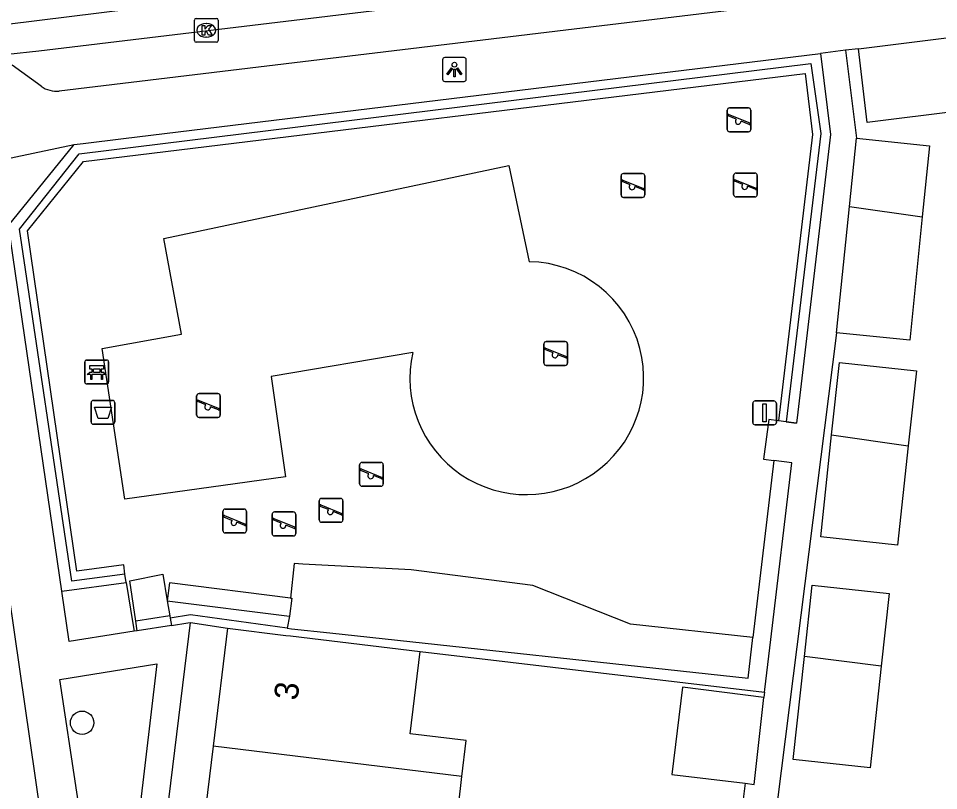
# Model space of a CAD drawing. Extents: x 162172 to 163187, y 382874 to 383684.
# Drawn here: x 162789.24 to 162827.76, y 383231.49 to 383263.83 of the extents above; entities that cross this region are included whole.
import ezdxf

# ---------------------------------------------------------------- set-up
doc = ezdxf.new("R2010")
doc.units = 0
for name, color, linetype in [('IMGEO_Afvalbak', 7, 'Continuous'), ('IMGEO_Bank', 7, 'Continuous'), ('IMGEO_Boom', 7, 'Continuous'), ('IMGEO_Groenvoorziening', 7, 'Continuous'), ('IMGEO_Haag', 7, 'Continuous'), ('IMGEO_Kolk', 7, 'Continuous'), ('IMGEO_Lichtpunt', 7, 'Continuous'), ('IMGEO_Pand', 7, 'Continuous'), ('IMGEO_Pand_nummerreeks', 7, 'Continuous'), ('IMGEO_Rijbaan_lokaal_gesloten', 7, 'Continuous'), ('IMGEO_Speelvoorziening', 7, 'Continuous'), ('IMGEO_Verkeersbordpaal', 7, 'Continuous'), ('IMGEO_Voetpad_open', 7, 'Continuous')]:
    doc.layers.add(name, color=color, linetype=linetype)

msp = doc.modelspace()

# ---------------------------------------------------------------- linework, layer by layer
at = {"layer": 'IMGEO_Afvalbak'}
for p, q in [((162792.286, 383246.932), (162792.286, 383247.732)), ((162792.286, 383247.732), (162792.286, 383246.932)), ((162792.386, 383247.832), (162793.176, 383247.832)), ((162793.176, 383247.832), (162792.386, 383247.832)), ((162793.276, 383247.732), (162793.276, 383246.932)), ((162793.276, 383246.932), (162793.276, 383247.732)), ((162793.176, 383246.832), (162792.386, 383246.832)), ((162792.386, 383246.832), (162793.176, 383246.832))]:
    msp.add_line(p, q, dxfattribs=at)
msp.add_lwpolyline([(162792.429, 383247.546), (162793.133, 383247.546), (162792.984, 383247.076), (162792.578, 383247.076), (162792.429, 383247.546)], dxfattribs=at)
for centre, start, end in [((162792.386, 383247.732), 90, 180), ((162792.386, 383247.732), 90, 180), ((162793.176, 383247.732), 0, 90), ((162793.176, 383247.732), 360, 90), ((162792.386, 383246.932), 180, 270), ((162792.386, 383246.932), 180, 270), ((162793.176, 383246.932), 270, 0), ((162793.176, 383246.932), 270, 0)]:
    msp.add_arc(centre, 0.1, start, end, dxfattribs=at)
at = {"layer": 'IMGEO_Bank'}
for p, q in [((162792.095, 383249.517), (162792.936, 383249.517)), ((162792.936, 383249.517), (162792.095, 383249.517)), ((162792.02, 383248.592), (162792.02, 383249.433)), ((162792.02, 383249.433), (162792.02, 383248.592)), ((162792.329, 383249.023), (162792.329, 383249.129)), ((162792.373, 383249.129), (162792.373, 383249.023)), ((162792.661, 383249.135), (162792.379, 383249.135)), ((162792.667, 383249.023), (162792.667, 383249.129)), ((162792.711, 383249.129), (162792.711, 383249.023)), ((162793.02, 383249.442), (162793.02, 383248.601)), ((162793.02, 383248.601), (162793.02, 383249.442)), ((162792.717, 383248.915), (162792.324, 383248.915)), ((162792.379, 383249.017), (162792.661, 383249.017)), ((162792.945, 383248.517), (162792.104, 383248.517)), ((162792.104, 383248.517), (162792.945, 383248.517))]:
    msp.add_line(p, q, dxfattribs=at)
for points in [[(162792.323, 383249.135), (162792.237, 383249.135), (162792.237, 383249.296), (162792.8, 383249.296), (162792.8, 383249.135), (162792.717, 383249.135)], [(162792.267, 383248.915), (162792.125, 383248.915), (162792.237, 383249.017), (162792.323, 383249.017)], [(162792.317, 383248.908), (162792.317, 383248.701), (162792.274, 383248.701), (162792.274, 383248.908)], [(162792.717, 383249.017), (162792.8, 383249.017), (162792.912, 383248.915), (162792.773, 383248.915)], [(162792.767, 383248.908), (162792.767, 383248.701), (162792.723, 383248.701), (162792.723, 383248.908)]]:
    msp.add_lwpolyline(points, dxfattribs=at)
for centre, radius, start, end in [((162792.098, 383249.439), 0.0779, 92.4484, 184.2845), ((162792.098, 383249.439), 0.0779, 92.4484, 184.2845), ((162792.942, 383249.439), 0.0779, 2.4484, 94.2845), ((162792.942, 383249.439), 0.0779, 2.4484, 94.2845), ((162792.322, 383249.128), 0.00671, 2.8957, 87.1043), ((162792.379, 383249.128), 0.00671, 92.8957, 177.1043), ((162792.661, 383249.128), 0.00671, 2.8957, 87.1043), ((162792.718, 383249.128), 0.00671, 92.8957, 177.1043), ((162792.267, 383248.908), 0.00671, 2.8957, 87.1043), ((162792.324, 383248.908), 0.00671, 92.8957, 177.1043), ((162792.322, 383249.024), 0.00671, 272.8957, 357.1043), ((162792.379, 383249.024), 0.00671, 182.8957, 267.1043), ((162792.661, 383249.024), 0.00671, 272.8957, 357.1043), ((162792.718, 383249.024), 0.00671, 182.8957, 267.1043), ((162792.716, 383248.908), 0.00671, 2.8957, 87.1043), ((162792.773, 383248.908), 0.00671, 92.8957, 177.1043), ((162792.098, 383248.595), 0.0779, 182.4484, 274.2845), ((162792.098, 383248.595), 0.0779, 182.4484, 274.2845), ((162792.942, 383248.595), 0.0779, 272.4484, 4.2845), ((162792.942, 383248.595), 0.0779, 272.4484, 4.2845)]:
    msp.add_arc(centre, radius, start, end, dxfattribs=at)
at = {"layer": 'IMGEO_Boom'}
msp.add_circle((162791.909, 383234.327), 0.489, dxfattribs=at)
at = {"layer": 'IMGEO_Groenvoorziening'}
for points in [[(162793.704, 383240.556), (162793.652, 383240.942), (162791.693, 383240.678), (162789.619, 383254.933), (162791.969, 383257.836), (162822.168, 383261.529), (162822.478, 383258.962), (162821.063, 383246.97)], [(162800.417, 383244.623), (162793.7, 383243.698), (162792.744, 383250), (162796.067, 383250.606), (162795.325, 383254.613), (162809.777, 383257.665), (162810.622, 383253.64)], [(162805.747, 383249.843), (162799.816, 383248.826), (162800.417, 383244.623)], [(162820.868, 383245.307), (162819.991, 383237.892)], [(162819.991, 383237.892), (162814.859, 383238.456), (162810.777, 383240.076), (162805.677, 383240.726), (162801.155, 383240.976), (162800.786, 383240.997), (162800.632, 383239.549)], [(162793.752, 383240.199), (162793.704, 383240.556)], [(162793.752, 383240.199), (162794.032, 383238.489), (162794.086, 383238.16)], [(162800.632, 383239.549), (162795.565, 383240.185), (162795.472, 383239.441)], [(162800.632, 383239.549), (162800.683, 383239.542), (162800.59, 383238.798)], [(162795.472, 383239.441), (162800.59, 383238.798)], [(162800.495, 383238.287), (162796.447, 383238.853), (162795.6, 383238.702)], [(162800.59, 383238.798), (162800.495, 383238.287)], [(162796.444, 383238.532), (162797.99, 383238.285)], [(162800.495, 383238.287), (162800.67, 383238.263), (162802.28, 383238.089), (162819.791, 383236.201), (162819.991, 383237.892)], [(162806.056, 383237.31), (162815.392, 383236.208), (162820.476, 383235.608)]]:
    msp.add_lwpolyline(points, dxfattribs=at)
for centre, radius, start, end in [((162810.545, 383248.77), 4.871, 14.6267, 89.0982), ((162810.547, 383248.773), 4.868, 304.4108, 14.5945), ((162810.51, 383248.766), 4.883, 167.2608, 304.8145)]:
    msp.add_arc(centre, radius, start, end, dxfattribs=at)
at = {"layer": 'IMGEO_Haag'}
for points in [[(162793.704, 383240.556), (162791.472, 383240.254), (162789.284, 383255.009), (162791.785, 383258.153), (162822.419, 383261.94), (162822.83, 383259.01), (162821.373, 383246.928)], [(162821.373, 383246.928), (162821.373, 383246.928), (162821.806, 383246.87)], [(162793.752, 383240.199), (162793.704, 383240.556), (162793.704, 383240.556)], [(162791.058, 383239.835), (162793.752, 383240.199)]]:
    msp.add_lwpolyline(points, dxfattribs=at)
at = {"layer": 'IMGEO_Kolk'}
for p, q in [((162796.682, 383263.831), (162797.534, 383263.831)), ((162796.607, 383262.905), (162796.607, 383263.757)), ((162797.095, 383263.611), (162797.12, 383263.611)), ((162797.608, 383263.757), (162797.608, 383262.905)), ((162797.118, 383263.051), (162797.093, 383263.051)), ((162797.534, 383262.831), (162796.682, 383262.831))]:
    msp.add_line(p, q, dxfattribs=at)
for points in [[(162796.682, 383263.831), (162797.534, 383263.831)], [(162796.607, 383262.905), (162796.607, 383263.757)], [(162796.928, 383263.531), (162797.051, 383263.531), (162797.051, 383263.38), (162797.181, 383263.531), (162797.345, 383263.531), (162797.199, 383263.38), (162797.352, 383263.131), (162797.2, 383263.131), (162797.115, 383263.295), (162797.051, 383263.228), (162797.051, 383263.131), (162796.928, 383263.131), (162796.928, 383263.531)], [(162797.608, 383263.757), (162797.608, 383262.905)], [(162797.534, 383262.831), (162796.682, 383262.831)]]:
    msp.add_lwpolyline(points, dxfattribs=at)
for centre, start, end in [((162796.684, 383263.755), 91.552, 178.448), ((162796.684, 383263.755), 91.552, 178.448), ((162797.532, 383263.755), 1.552, 88.448), ((162797.532, 383263.755), 1.552, 88.448), ((162796.684, 383262.907), 181.552, 268.448), ((162796.684, 383262.907), 181.552, 268.448), ((162797.532, 383262.907), 271.552, 358.448), ((162797.532, 383262.907), 271.552, 358.448)]:
    msp.add_arc(centre, 0.0765, start, end, dxfattribs=at)
for centre, major_axis, ratio, start_param, end_param in [((162797.094, 383263.331), (-0.387, 0.002), 0.722429, 4.712389, 7.853982), ((162797.119, 383263.331), (-0.39, 0.002), 0.717154, 1.570796, 4.712389)]:
    msp.add_ellipse(centre, major_axis=major_axis, ratio=ratio, start_param=start_param, end_param=end_param, dxfattribs=at)
at = {"layer": 'IMGEO_Lichtpunt'}
for p, q in [((162806.995, 383262.094), (162806.995, 383261.287)), ((162806.995, 383262.094), (162806.995, 383261.287)), ((162807.897, 383262.189), (162807.089, 383262.189)), ((162807.897, 383262.189), (162807.089, 383262.189)), ((162807.991, 383261.287), (162807.991, 383262.094)), ((162807.991, 383261.287), (162807.991, 383262.094)), ((162807.089, 383261.193), (162807.897, 383261.193)), ((162807.089, 383261.193), (162807.897, 383261.193))]:
    msp.add_line(p, q, dxfattribs=at)
for points in [[(162807.369, 383261.758), (162807.408, 383261.73), (162807.22, 383261.468), (162807.182, 383261.495), (162807.369, 383261.758)], [(162807.471, 383261.71), (162807.518, 383261.71), (162807.518, 383261.388), (162807.471, 383261.388), (162807.471, 383261.71)], [(162807.581, 383261.73), (162807.619, 383261.757), (162807.806, 383261.495), (162807.767, 383261.467), (162807.581, 383261.73)]]:
    msp.add_lwpolyline(points, dxfattribs=at)
msp.add_circle((162807.494, 383261.892), 0.0994, dxfattribs=at)
for centre, start, end in [((162807.089, 383262.094), 90, 180), ((162807.089, 383262.094), 90, 180), ((162807.897, 383262.094), 0, 90), ((162807.897, 383262.094), 0, 90), ((162807.089, 383261.287), 180, 270), ((162807.089, 383261.287), 180, 270), ((162807.897, 383261.287), 270, 0), ((162807.897, 383261.287), 270, 360)]:
    msp.add_arc(centre, 0.0946, start, end, dxfattribs=at)
at = {"layer": 'IMGEO_Pand'}
for points in [[(162828.315, 383263.05), (162828.687, 383259.953), (162824.766, 383259.472), (162824.408, 383262.562)], [(162824.408, 383262.562), (162828.315, 383263.05)], [(162824.027, 383255.955), (162824.317, 383258.81)], [(162824.317, 383258.81), (162827.382, 383258.498), (162827.079, 383255.514)], [(162823.489, 383250.661), (162824.027, 383255.955)], [(162824.027, 383255.955), (162827.079, 383255.514)], [(162827.079, 383255.514), (162826.554, 383250.349), (162823.489, 383250.661)], [(162823.284, 383246.388), (162823.611, 383249.423), (162826.833, 383249.074), (162826.493, 383245.924)], [(162826.493, 383245.924), (162826.045, 383241.77), (162822.824, 383242.119), (162823.284, 383246.388)], [(162823.284, 383246.388), (162826.493, 383245.924)], [(162822.142, 383237.097), (162822.465, 383240.093), (162825.687, 383239.744), (162825.359, 383236.701)], [(162797.99, 383238.285), (162797.392, 383233.343)], [(162797.99, 383238.285), (162800.439, 383237.989), (162800.634, 383237.965), (162806.056, 383237.31)], [(162807.808, 383232.082), (162807.989, 383233.582), (162805.64, 383233.866), (162806.056, 383237.31)], [(162825.359, 383236.701), (162824.899, 383232.44), (162821.678, 383232.789), (162822.142, 383237.097)], [(162825.359, 383236.701), (162822.142, 383237.097)], [(162820.451, 383235.387), (162817.047, 383235.815), (162816.59, 383232.164), (162819.667, 383231.792)], [(162819.667, 383231.792), (162820.039, 383231.747), (162820.451, 383235.387)], [(162797.392, 383233.343), (162796.854, 383228.896)], [(162807.808, 383232.082), (162797.392, 383233.343)], [(162804.921, 383227.92), (162805.308, 383231.124), (162807.658, 383230.84), (162807.808, 383232.082)]]:
    msp.add_lwpolyline(points, dxfattribs=at)
at = {"layer": 'IMGEO_Rijbaan_lokaal_gesloten'}
for points in [[(162746.988, 383284.773), (162754.973, 383275.848), (162761.671, 383268.445), (162764.865, 383265.64), (162770.006, 383263.146), (162774.835, 383262.367), (162778.262, 383262.289), (162808.407, 383266.029), (162835.747, 383269.38), (162863.477, 383272.809), (162911.477, 383279.327), (162911.844, 383279.376), (162920.076, 383280.478)], [(162787.483, 383262.198), (162790.095, 383262.473), (162819.027, 383265.957), (162822.009, 383266.344), (162848.142, 383269.478)]]:
    msp.add_lwpolyline(points, dxfattribs=at)
at = {"layer": 'IMGEO_Speelvoorziening'}
for p, q in [((162818.91, 383259.181), (162818.91, 383259.981)), ((162818.91, 383259.981), (162818.91, 383259.181)), ((162819.01, 383260.081), (162819.8, 383260.081)), ((162819.8, 383260.081), (162819.01, 383260.081)), ((162819.9, 383259.981), (162819.9, 383259.181)), ((162819.9, 383259.181), (162819.9, 383259.981)), ((162819.293, 383259.609), (162818.954, 383259.746)), ((162818.979, 383259.806), (162819.855, 383259.453)), ((162819.831, 383259.393), (162819.491, 383259.53)), ((162819.8, 383259.081), (162819.01, 383259.081)), ((162819.01, 383259.081), (162819.8, 383259.081)), ((162814.469, 383256.434), (162814.469, 383257.234)), ((162814.469, 383257.234), (162814.469, 383256.434)), ((162814.569, 383257.334), (162815.359, 383257.334)), ((162815.359, 383257.334), (162814.569, 383257.334)), ((162815.459, 383257.234), (162815.459, 383256.434)), ((162815.459, 383256.434), (162815.459, 383257.234)), ((162819.182, 383256.45), (162819.182, 383257.25)), ((162819.182, 383257.25), (162819.182, 383256.45)), ((162819.282, 383257.35), (162820.072, 383257.35)), ((162820.072, 383257.35), (162819.282, 383257.35)), ((162820.172, 383257.25), (162820.172, 383256.45)), ((162820.172, 383256.45), (162820.172, 383257.25)), ((162814.852, 383256.862), (162814.513, 383256.999)), ((162814.538, 383257.059), (162815.414, 383256.706)), ((162819.565, 383256.878), (162819.226, 383257.015)), ((162819.251, 383257.075), (162820.127, 383256.722)), ((162815.39, 383256.646), (162815.05, 383256.783)), ((162820.103, 383256.662), (162819.763, 383256.799)), ((162815.359, 383256.334), (162814.569, 383256.334)), ((162814.569, 383256.334), (162815.359, 383256.334)), ((162820.072, 383256.35), (162819.282, 383256.35)), ((162819.282, 383256.35), (162820.072, 383256.35)), ((162811.339, 383250.295), (162812.129, 383250.295)), ((162812.129, 383250.295), (162811.339, 383250.295)), ((162811.239, 383249.395), (162811.239, 383250.195)), ((162811.239, 383250.195), (162811.239, 383249.395)), ((162811.622, 383249.823), (162811.283, 383249.96)), ((162811.308, 383250.02), (162812.184, 383249.667)), ((162812.229, 383250.195), (162812.229, 383249.395)), ((162812.229, 383249.395), (162812.229, 383250.195)), ((162812.16, 383249.607), (162811.82, 383249.744)), ((162812.129, 383249.295), (162811.339, 383249.295)), ((162811.339, 383249.295), (162812.129, 383249.295)), ((162796.704, 383247.216), (162796.704, 383248.016)), ((162796.704, 383248.016), (162796.704, 383247.216)), ((162796.804, 383248.116), (162797.594, 383248.116)), ((162797.594, 383248.116), (162796.804, 383248.116)), ((162797.694, 383248.016), (162797.694, 383247.216)), ((162797.694, 383247.216), (162797.694, 383248.016)), ((162797.087, 383247.644), (162796.748, 383247.781)), ((162796.773, 383247.841), (162797.649, 383247.488)), ((162797.625, 383247.428), (162797.285, 383247.565)), ((162797.594, 383247.116), (162796.804, 383247.116)), ((162796.804, 383247.116), (162797.594, 383247.116)), ((162803.527, 383244.332), (162803.527, 383245.132)), ((162803.527, 383245.132), (162803.527, 383244.332)), ((162803.91, 383244.76), (162803.571, 383244.897)), ((162803.596, 383244.957), (162804.472, 383244.604)), ((162803.627, 383245.232), (162804.417, 383245.232)), ((162804.417, 383245.232), (162803.627, 383245.232)), ((162804.517, 383245.132), (162804.517, 383244.332)), ((162804.517, 383244.332), (162804.517, 383245.132)), ((162804.448, 383244.544), (162804.108, 383244.681)), ((162804.417, 383244.232), (162803.627, 383244.232)), ((162803.627, 383244.232), (162804.417, 383244.232)), ((162801.835, 383242.827), (162801.835, 383243.627)), ((162801.835, 383243.627), (162801.835, 383242.827)), ((162802.218, 383243.255), (162801.879, 383243.392)), ((162801.904, 383243.452), (162802.78, 383243.099)), ((162801.935, 383243.727), (162802.725, 383243.727)), ((162802.725, 383243.727), (162801.935, 383243.727)), ((162802.825, 383243.627), (162802.825, 383242.827)), ((162802.825, 383242.827), (162802.825, 383243.627)), ((162797.8, 383242.378), (162797.8, 383243.178)), ((162797.8, 383243.178), (162797.8, 383242.378)), ((162797.869, 383243.003), (162798.745, 383242.65)), ((162797.9, 383243.278), (162798.69, 383243.278)), ((162798.69, 383243.278), (162797.9, 383243.278)), ((162798.79, 383243.178), (162798.79, 383242.378)), ((162798.79, 383242.378), (162798.79, 383243.178)), ((162799.86, 383242.256), (162799.86, 383243.056)), ((162799.86, 383243.056), (162799.86, 383242.256)), ((162799.96, 383243.156), (162800.75, 383243.156)), ((162800.75, 383243.156), (162799.96, 383243.156)), ((162800.85, 383243.056), (162800.85, 383242.256)), ((162800.85, 383242.256), (162800.85, 383243.056)), ((162802.756, 383243.039), (162802.416, 383243.176)), ((162798.183, 383242.806), (162797.844, 383242.943)), ((162798.721, 383242.59), (162798.381, 383242.727)), ((162800.243, 383242.684), (162799.904, 383242.821)), ((162799.929, 383242.881), (162800.805, 383242.528)), ((162800.781, 383242.468), (162800.441, 383242.605)), ((162802.725, 383242.727), (162801.935, 383242.727)), ((162801.935, 383242.727), (162802.725, 383242.727)), ((162798.69, 383242.278), (162797.9, 383242.278)), ((162797.9, 383242.278), (162798.69, 383242.278)), ((162800.75, 383242.156), (162799.96, 383242.156)), ((162799.96, 383242.156), (162800.75, 383242.156))]:
    msp.add_line(p, q, dxfattribs=at)
for centre, radius, start, end in [((162819.01, 383259.981), 0.1, 90, 180), ((162819.01, 383259.981), 0.1, 90, 180), ((162819.8, 383259.981), 0.1, 0, 90), ((162819.8, 383259.981), 0.1, 360, 90), ((162818.967, 383259.776), 0.0327, 68.078, 248.078), ((162819.372, 383259.519), 0.12, 130.9928, 5.1632), ((162819.01, 383259.181), 0.1, 180, 270), ((162819.01, 383259.181), 0.1, 180, 270), ((162819.8, 383259.181), 0.1, 270, 0), ((162819.8, 383259.181), 0.1, 270, 0), ((162819.843, 383259.423), 0.0327, 248.078, 68.078), ((162814.569, 383257.234), 0.1, 90, 180), ((162814.569, 383257.234), 0.1, 90, 180), ((162815.359, 383257.234), 0.1, 0, 90), ((162815.359, 383257.234), 0.1, 360, 90), ((162819.282, 383257.25), 0.1, 90, 180), ((162819.282, 383257.25), 0.1, 90, 180), ((162820.072, 383257.25), 0.1, 0, 90), ((162820.072, 383257.25), 0.1, 360, 90), ((162814.526, 383257.029), 0.0327, 68.078, 248.078), ((162814.931, 383256.772), 0.12, 130.9928, 5.1632), ((162819.239, 383257.045), 0.0327, 68.078, 248.078), ((162819.644, 383256.788), 0.12, 130.9928, 5.1632), ((162815.402, 383256.676), 0.0327, 248.078, 68.078), ((162819.282, 383256.45), 0.1, 180, 270), ((162819.282, 383256.45), 0.1, 180, 270), ((162820.072, 383256.45), 0.1, 270, 0), ((162820.072, 383256.45), 0.1, 270, 0), ((162820.115, 383256.692), 0.0327, 248.078, 68.078), ((162814.569, 383256.434), 0.1, 180, 270), ((162814.569, 383256.434), 0.1, 180, 270), ((162815.359, 383256.434), 0.1, 270, 0), ((162815.359, 383256.434), 0.1, 270, 0), ((162811.339, 383250.195), 0.1, 90, 180), ((162811.339, 383250.195), 0.1, 90, 180), ((162812.129, 383250.195), 0.1, 0, 90), ((162812.129, 383250.195), 0.1, 360, 90), ((162811.296, 383249.99), 0.0327, 68.078, 248.078), ((162811.701, 383249.733), 0.12, 130.9928, 5.1632), ((162812.172, 383249.637), 0.0327, 248.078, 68.078), ((162811.339, 383249.395), 0.1, 180, 270), ((162811.339, 383249.395), 0.1, 180, 270), ((162812.129, 383249.395), 0.1, 270, 0), ((162812.129, 383249.395), 0.1, 270, 0), ((162796.804, 383248.016), 0.1, 90, 180), ((162796.804, 383248.016), 0.1, 90, 180), ((162797.594, 383248.016), 0.1, 0, 90), ((162797.594, 383248.016), 0.1, 360, 90), ((162796.761, 383247.811), 0.0327, 68.078, 248.078), ((162797.166, 383247.554), 0.12, 130.9928, 5.1632), ((162796.804, 383247.216), 0.1, 180, 270), ((162796.804, 383247.216), 0.1, 180, 270), ((162797.594, 383247.216), 0.1, 270, 0), ((162797.594, 383247.216), 0.1, 270, 0), ((162797.637, 383247.458), 0.0327, 248.078, 68.078), ((162803.627, 383245.132), 0.1, 90, 180), ((162803.627, 383245.132), 0.1, 90, 180), ((162803.584, 383244.927), 0.0327, 68.078, 248.078), ((162804.417, 383245.132), 0.1, 0, 90), ((162804.417, 383245.132), 0.1, 360, 90), ((162803.989, 383244.67), 0.12, 130.9928, 5.1632), ((162804.46, 383244.574), 0.0327, 248.078, 68.078), ((162803.627, 383244.332), 0.1, 180, 270), ((162803.627, 383244.332), 0.1, 180, 270), ((162804.417, 383244.332), 0.1, 270, 0), ((162804.417, 383244.332), 0.1, 270, 0), ((162801.935, 383243.627), 0.1, 90, 180), ((162801.935, 383243.627), 0.1, 90, 180), ((162801.892, 383243.422), 0.0327, 68.078, 248.078), ((162802.725, 383243.627), 0.1, 0, 90), ((162802.725, 383243.627), 0.1, 360, 90), ((162797.9, 383243.178), 0.1, 90, 180), ((162797.9, 383243.178), 0.1, 90, 180), ((162797.857, 383242.973), 0.0327, 68.078, 248.078), ((162798.69, 383243.178), 0.1, 0, 90), ((162798.69, 383243.178), 0.1, 360, 90), ((162799.96, 383243.056), 0.1, 90, 180), ((162799.96, 383243.056), 0.1, 90, 180), ((162800.75, 383243.056), 0.1, 0, 90), ((162800.75, 383243.056), 0.1, 360, 90), ((162802.297, 383243.165), 0.12, 130.9928, 5.1632), ((162802.768, 383243.069), 0.0327, 248.078, 68.078), ((162798.262, 383242.716), 0.12, 130.9928, 5.1632), ((162798.733, 383242.62), 0.0327, 248.078, 68.078), ((162799.917, 383242.851), 0.0327, 68.078, 248.078), ((162800.322, 383242.594), 0.12, 130.9928, 5.1632), ((162801.935, 383242.827), 0.1, 180, 270), ((162801.935, 383242.827), 0.1, 180, 270), ((162802.725, 383242.827), 0.1, 270, 0), ((162802.725, 383242.827), 0.1, 270, 0), ((162797.9, 383242.378), 0.1, 180, 270), ((162797.9, 383242.378), 0.1, 180, 270), ((162798.69, 383242.378), 0.1, 270, 0), ((162798.69, 383242.378), 0.1, 270, 0), ((162799.96, 383242.256), 0.1, 180, 270), ((162799.96, 383242.256), 0.1, 180, 270), ((162800.75, 383242.256), 0.1, 270, 0), ((162800.75, 383242.256), 0.1, 270, 0), ((162800.793, 383242.498), 0.0327, 248.078, 68.078)]:
    msp.add_arc(centre, radius, start, end, dxfattribs=at)
at = {"layer": 'IMGEO_Verkeersbordpaal'}
for p, q in [((162819.979, 383246.906), (162819.979, 383247.706)), ((162819.979, 383247.706), (162819.979, 383246.906)), ((162820.079, 383247.806), (162820.869, 383247.806)), ((162820.869, 383247.806), (162820.079, 383247.806)), ((162820.969, 383247.706), (162820.969, 383246.906)), ((162820.969, 383246.906), (162820.969, 383247.706)), ((162820.869, 383246.806), (162820.079, 383246.806)), ((162820.079, 383246.806), (162820.869, 383246.806))]:
    msp.add_line(p, q, dxfattribs=at)
msp.add_lwpolyline([(162820.399, 383247.681), (162820.549, 383247.681), (162820.549, 383246.931), (162820.399, 383246.931), (162820.399, 383247.681)], dxfattribs=at)
for centre, start, end in [((162820.079, 383247.706), 90, 180), ((162820.079, 383247.706), 90, 180), ((162820.869, 383247.706), 0, 90), ((162820.869, 383247.706), 360, 90), ((162820.079, 383246.906), 180, 270), ((162820.079, 383246.906), 180, 270), ((162820.869, 383246.906), 270, 0), ((162820.869, 383246.906), 270, 0)]:
    msp.add_arc(centre, 0.1, start, end, dxfattribs=at)
at = {"layer": 'IMGEO_Voetpad_open'}
for points in [[(162831.393, 383265.672), (162790.95, 383260.785)], [(162791.577, 383258.544), (162791.954, 383258.59), (162793.646, 383258.798), (162822.823, 383262.365)], [(162822.823, 383262.365), (162823.233, 383258.963), (162821.862, 383247.341), (162821.806, 383246.87)], [(162823.859, 383262.494), (162822.823, 383262.365)], [(162824.408, 383262.562), (162823.859, 383262.494)], [(162823.859, 383262.494), (162824.317, 383258.81)], [(162790.197, 383260.987), (162788.975, 383261.867)], [(162784.237, 383257.006), (162791.577, 383258.544)], [(162791.058, 383239.835), (162788.83, 383255.15), (162791.577, 383258.544)], [(162823.489, 383250.661), (162820.019, 383223.136), (162832.524, 383221.545)], [(162821.063, 383246.97), (162820.649, 383247.025), (162820.427, 383245.366), (162820.868, 383245.307)], [(162821.373, 383246.928), (162821.063, 383246.97)], [(162821.806, 383246.87), (162821.373, 383246.928)], [(162820.476, 383235.608), (162820.492, 383235.719), (162820.739, 383237.81), (162821.611, 383245.208), (162820.868, 383245.307)], [(162788.168, 383244.227), (162791.474, 383221.369)], [(162794.16, 383238.581), (162793.903, 383240.276), (162795.282, 383240.555), (162795.472, 383239.441)], [(162794.086, 383238.16), (162793.472, 383238.063), (162791.364, 383237.731), (162791.058, 383239.835)], [(162795.472, 383239.441), (162795.58, 383238.81)], [(162795.58, 383238.81), (162794.16, 383238.581)], [(162795.58, 383238.81), (162795.6, 383238.702)], [(162792.986, 383209.886), (162793.442, 383213.879), (162794.777, 383224.846), (162796.374, 383237.96), (162796.444, 383238.532)], [(162794.22, 383238.181), (162794.16, 383238.581)], [(162795.654, 383238.407), (162794.22, 383238.181)], [(162795.6, 383238.702), (162795.654, 383238.407)], [(162795.654, 383238.407), (162796.334, 383238.515), (162796.444, 383238.532)], [(162794.22, 383238.181), (162794.086, 383238.16)], [(162790.981, 383236.14), (162795.034, 383236.795), (162793.818, 383226.51), (162792.399, 383226.694), (162790.981, 383236.14)], [(162820.476, 383235.608), (162820.451, 383235.387)], [(162819.667, 383231.792), (162819.413, 383229.783)]]:
    msp.add_lwpolyline(points, dxfattribs=at)
msp.add_arc((162790.844, 383261.893), 1.113, 234.4886, 275.4782, dxfattribs=at)

# ---------------------------------------------------------------- texts
at = {"layer": 'IMGEO_Pand_nummerreeks'}
msp.add_text('3', height=1, rotation=83.1041, dxfattribs=at).set_placement((162800.925, 383235.236))

doc.saveas('drawing.dxf')
